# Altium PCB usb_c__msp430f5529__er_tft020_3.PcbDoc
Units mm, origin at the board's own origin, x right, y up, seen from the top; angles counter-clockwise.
Board outline 82 x 52 mm, 2 copper layers (Top, Bottom), stack 0 mm thick; 32 components, 32 nets, 197 pads, 82 vias.
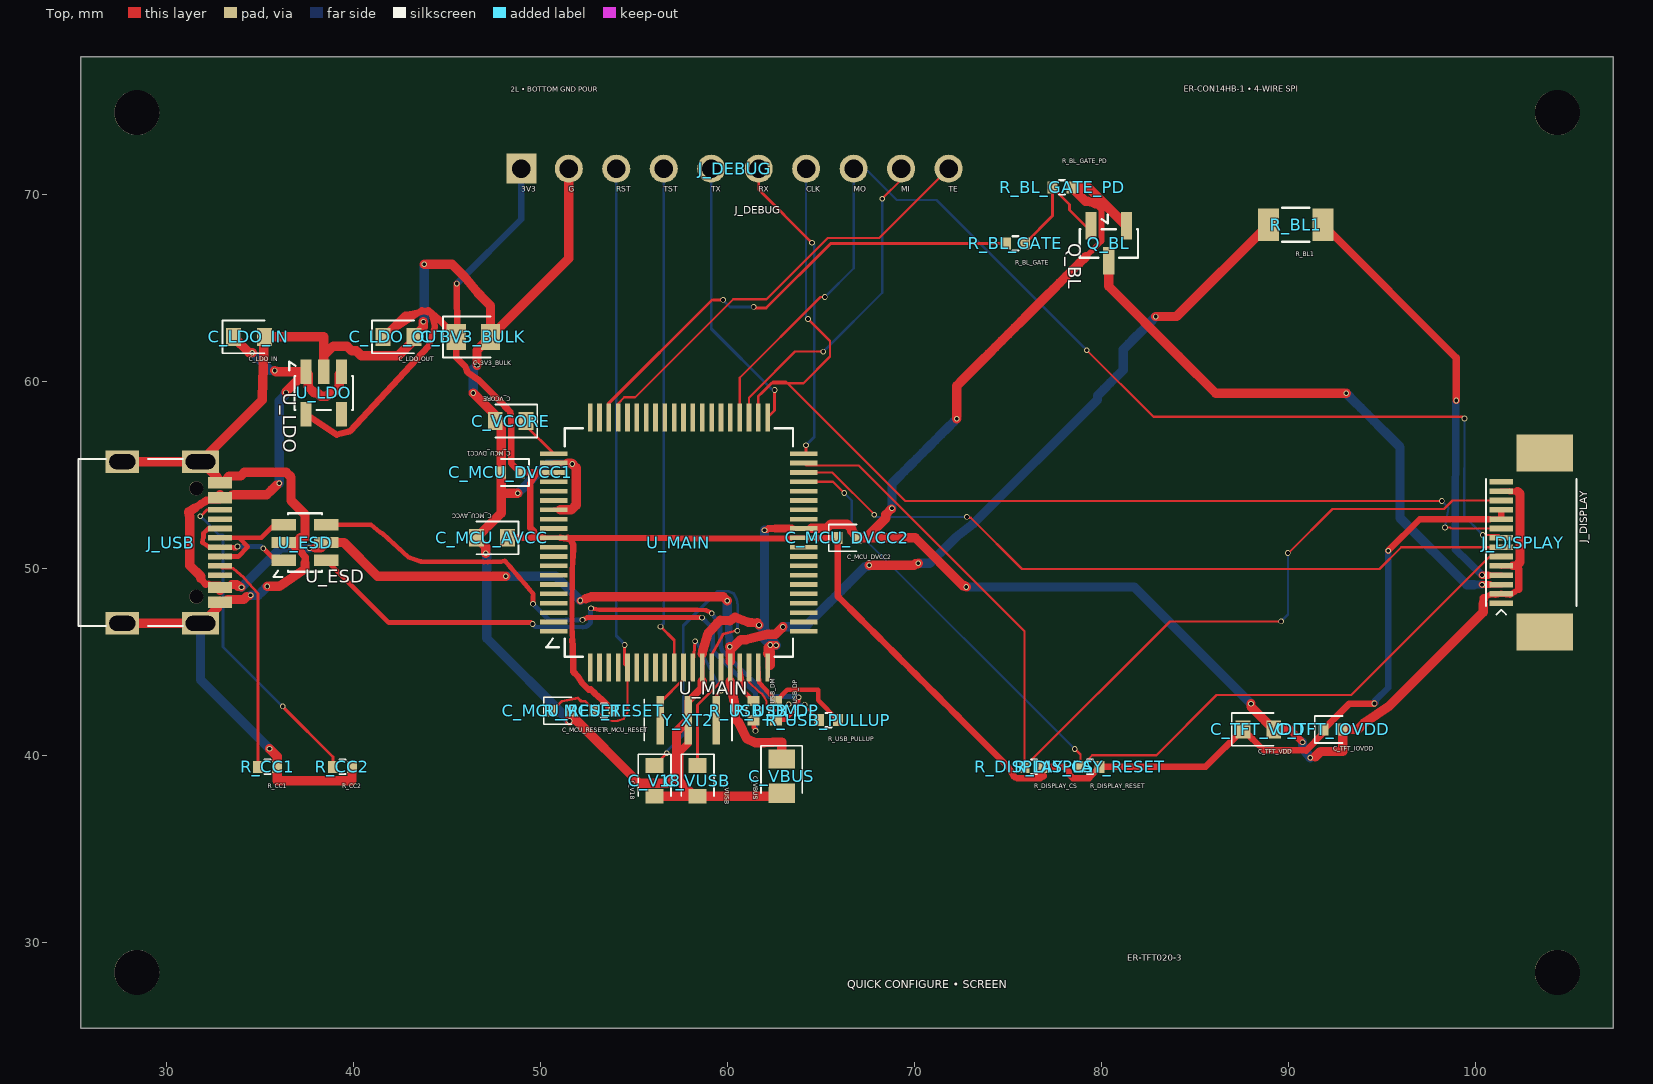
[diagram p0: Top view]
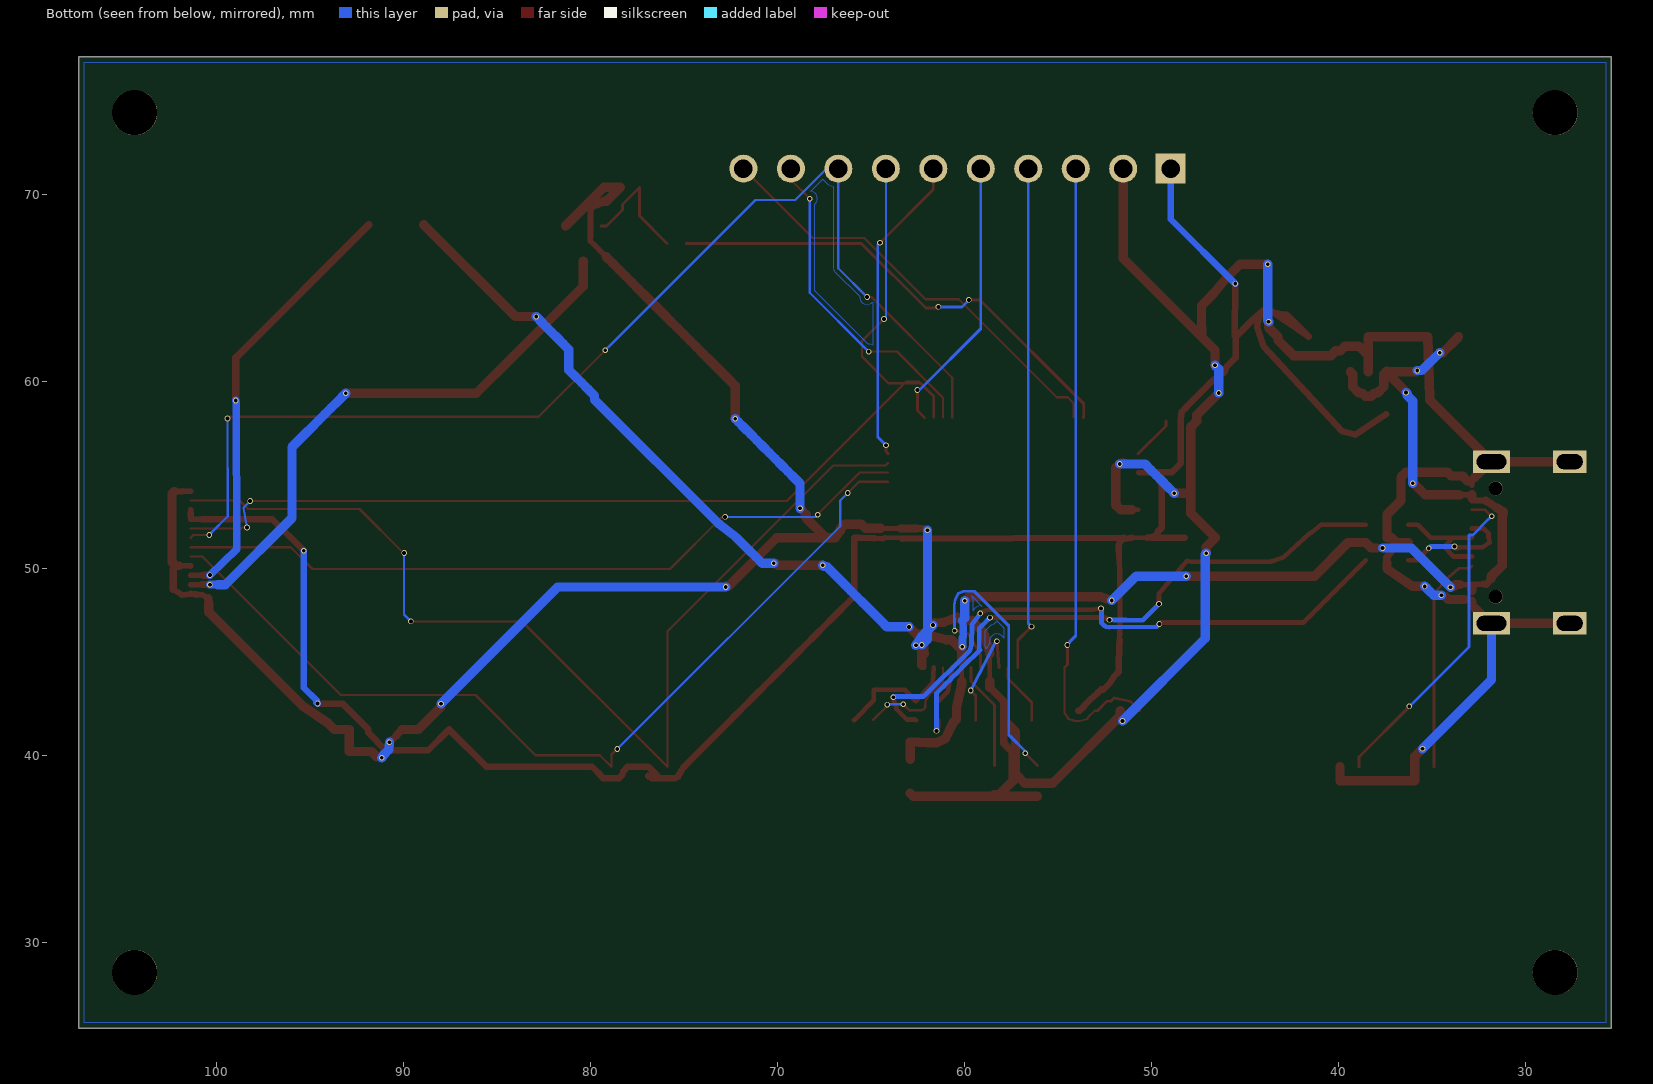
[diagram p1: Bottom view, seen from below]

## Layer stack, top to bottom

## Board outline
25.4,77.4 107.4,77.4 107.4,25.4 25.4,25.4

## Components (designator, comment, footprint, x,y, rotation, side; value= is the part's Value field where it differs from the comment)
C_3V3_BULK "" TSCIRCUIT-2.8500x1.4000mm 46.4,62.4 r0 top
C_LDO_IN "" TSCIRCUIT-2.4500x0.9500mm 34.4,62.4 r0 top
C_LDO_OUT "" TSCIRCUIT-2.4500x0.9500mm 42.4,62.4 r0 top
C_MCU_AVCC "" TSCIRCUIT-2.4500x0.9500mm 47.4,51.65 r180 top
C_MCU_DVCC1 "" TSCIRCUIT-1.5600x0.6400mm 48.4,55.15 r180 top
C_MCU_DVCC2 "" TSCIRCUIT-1.5600x0.6400mm 66.4,51.65 r0 top
C_MCU_RESET "" TSCIRCUIT-1.5600x0.6400mm 51.15,42.4 r0 top
C_TFT_IOVDD "" TSCIRCUIT-1.5600x0.6400mm 92.4,41.4 r0 top
C_TFT_VDD "" TSCIRCUIT-2.4500x0.9500mm 88.4,41.4 r0 top
C_V18 "" TSCIRCUIT-0.9500x2.4500mm 56.1,38.65 r270 top
C_VBUS "" TSCIRCUIT-1.4000x2.8500mm 62.9,38.9 r270 top
C_VCORE "" TSCIRCUIT-2.4500x0.9500mm 48.4,57.9 r180 top
C_VUSB "" TSCIRCUIT-0.9500x2.4500mm 58.4,38.65 r270 top
J_DEBUG "" TSCIRCUIT-24.3600x1.5000mm 60.4,71.4 r0 top
J_DISPLAY "" TSCIRCUIT-4.4500x11.5800mm 103,51.4 r90 top
J_USB "" TSCIRCUIT-6.7732x9.8502mm 30.113,51.4 r90 top
Q_BL "" TSCIRCUIT-2.5000x3.3500mm 80.4,67.4 r270 top
R_BL1 "" TSCIRCUIT-4.0500x1.7500mm 90.4,68.4 r0 top
R_BL_GATE "" TSCIRCUIT-1.5600x0.6400mm 75.4,67.4 r0 top
R_BL_GATE_PD "" TSCIRCUIT-1.5600x0.6400mm 77.9,70.4 r0 top
R_CC1 "" TSCIRCUIT-1.5600x0.6400mm 35.4,39.4 r0 top
R_CC2 "" TSCIRCUIT-1.5600x0.6400mm 39.4,39.4 r0 top
R_DISPLAY_CS "" TSCIRCUIT-1.5600x0.6400mm 76.4,39.4 r0 top
R_DISPLAY_RESET "" TSCIRCUIT-1.5600x0.6400mm 79.4,39.4 r0 top
R_MCU_RESET "" TSCIRCUIT-1.5600x0.6400mm 53.4,42.4 r0 top
R_USB_DM "" TSCIRCUIT-0.6400x1.5600mm 61.4,42.4 r90 top
R_USB_DP "" TSCIRCUIT-0.6400x1.5600mm 62.6,42.4 r90 top
R_USB_PULLUP "" TSCIRCUIT-1.5600x0.6400mm 65.4,41.9 r0 top
U_ESD "" TSCIRCUIT-3.6000x2.5000mm 37.4,51.4 r0 top
U_LDO "" TSCIRCUIT-2.5000x3.6000mm 38.4,59.4 r270 top
U_MAIN "" TSCIRCUIT-14.8500x14.8500mm 57.4,51.4 r0 top
Y_XT2 "" TSCIRCUIT-3.4000x2.6000mm 57.9,41.9 r270 top

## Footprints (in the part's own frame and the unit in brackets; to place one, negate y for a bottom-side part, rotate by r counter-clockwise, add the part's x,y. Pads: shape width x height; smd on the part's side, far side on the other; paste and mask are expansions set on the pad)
TSCIRCUIT-0.6400x1.5600mm [mm]
  rect 0.54x0.64 smd: 1(-0.51,0) 2(0.51,0)
  silkscreen extent -0.15,-0.38 0.15,0.38
TSCIRCUIT-0.9500x2.4500mm [mm]
  rect 0.8x0.95 smd: 1(-0.825,0) 2(0.825,0)
  silkscreen extent -1.43,-0.87 0.82,0.87
TSCIRCUIT-1.4000x2.8500mm [mm]
  rect 1.025x1.4 smd: 1(-0.913,0) 2(0.913,0)
  silkscreen extent -1.62,-1.1 0.91,1.1
TSCIRCUIT-1.5600x0.6400mm [mm]
  rect 0.54x0.64 smd: 1(-0.51,0) 2(0.51,0)
  silkscreen extent -0.98,-0.72 0.51,0.72
TSCIRCUIT-2.4500x0.9500mm [mm]
  rect 0.8x0.95 smd: 1(-0.825,0) 2(0.825,0)
  silkscreen extent -1.43,-0.87 0.82,0.87
TSCIRCUIT-2.5000x3.3500mm [mm]
  rect 1.475x0.6 smd: 1(-0.938,-0.95) 2(-0.938,0.95) 3(0.937,0)
  silkscreen extent -1.54,-1.56 0.76,1.56
TSCIRCUIT-2.5000x3.6000mm [mm]
  rect 1.325x0.6 smd: 1(-1.137,-0.95) 2(-1.137,0) 3(-1.137,0.95) 4(1.138,0.95) 5(1.138,-0.95)
  silkscreen extent -1.69,-1.84 0.91,1.56
TSCIRCUIT-2.8500x1.4000mm [mm]
  rect 1.025x1.4 smd: 1(-0.913,0) 2(0.913,0)
  silkscreen extent -1.63,-1.1 0.91,1.1
TSCIRCUIT-3.4000x2.6000mm [mm]
  rect 2.6x0.4 smd: 1(0,1.5) 2(0,0) 3(0,-1.5)
  silkscreen extent -1.1,-2.35 1.1,2.35
TSCIRCUIT-3.6000x2.5000mm [mm]
  rect 1.325x0.6 smd: 1(-1.137,-0.95) 2(-1.137,0) 3(-1.137,0.95) 4(1.138,0.95) 5(1.138,0) 6(1.138,-0.95)
  silkscreen extent -1.69,-1.84 0.91,1.56
TSCIRCUIT-4.0500x1.7500mm [mm]
  rect 1.125x1.75 smd: 1(-1.462,0) 2(1.463,0)
  silkscreen extent -0.73,-0.91 0.73,0.91
TSCIRCUIT-4.4500x11.5800mm [mm]
  rect 0.3x1.25 smd: 1(-3.25,1.6) 2(-2.75,1.6) 3(-2.25,1.6) 4(-1.75,1.6) 5(-1.25,1.6) 6(-0.75,1.6) 7(-0.25,1.6) 8(0.25,1.6) 9(0.75,1.6) 10(1.25,1.6) 11(1.75,1.6) 12(2.25,1.6) 13(2.75,1.6) 14(3.25,1.6)
  rect 2x3 smd: 15(4.79,-0.725) 16(-4.79,-0.725)
  silkscreen extent -3.85,-2.43 3.4,2.42
TSCIRCUIT-6.7732x9.8502mm [mm]
  rect 0.3x1.3 smd: 1(-3.35,-2.737) 2(-3.05,-2.737) 3(-2.55,-2.737) 4(-2.25,-2.737) 5(-1.75,-2.737) 6(-1.25,-2.737) 7(-0.75,-2.737) 8(-0.25,-2.737) 9(0.25,-2.737) 10(0.75,-2.737) 11(1.25,-2.737) 12(1.75,-2.737) 13(2.55,-2.737) 14(2.25,-2.737) 15(3.35,-2.737) 16(3.05,-2.737)
  rect 1.2x2 hole 0.8 slot 1.6 at 90 deg: 17(-4.325,-1.693) 18(4.325,-1.693)
  rect 1.2x1.8 hole 0.8 slot 1.4 at 90 deg: 19(4.325,2.487) 20(-4.325,2.487)
  round 0.75 hole 0.75 unplated: NPTH-1(-2.9,-1.468) NPTH-2(2.9,-1.468)
  silkscreen extent -4.47,-0.75 4.47,4.83
TSCIRCUIT-14.8500x14.8500mm [mm]
  rect 1.475x0.25 smd: 1(-6.687,-4.75) 2(-6.687,-4.25) 3(-6.687,-3.75) 4(-6.687,-3.25) 5(-6.687,-2.75) 6(-6.687,-2.25) 7(-6.687,-1.75) 8(-6.687,-1.25) 9(-6.687,-0.75) 10(-6.687,-0.25) 11(-6.687,0.25) 12(-6.687,0.75) 13(-6.687,1.25) 14(-6.687,1.75) 15(-6.687,2.25) 16(-6.687,2.75) 17(-6.687,3.25) 18(-6.687,3.75) 19(-6.687,4.25) 20(-6.687,4.75) 41(6.687,4.75) 42(6.687,4.25) 43(6.687,3.75) 44(6.687,3.25) 45(6.687,2.75) 46(6.687,2.25) 47(6.687,1.75) 48(6.687,1.25) 49(6.687,0.75) 50(6.687,0.25) 51(6.687,-0.25) 52(6.687,-0.75) 53(6.687,-1.25) 54(6.687,-1.75) 55(6.687,-2.25) 56(6.687,-2.75) 57(6.687,-3.25) 58(6.687,-3.75) 59(6.687,-4.25) 60(6.687,-4.75)
  rect 0.25x1.475 smd: 21(-4.75,6.687) 22(-4.25,6.687) 23(-3.75,6.687) 24(-3.25,6.687) 25(-2.75,6.687) 26(-2.25,6.687) 27(-1.75,6.687) 28(-1.25,6.687) 29(-0.75,6.687) 30(-0.25,6.687) 31(0.25,6.687) 32(0.75,6.687) 33(1.25,6.687) 34(1.75,6.687) 35(2.25,6.687) 36(2.75,6.687) 37(3.25,6.687) 38(3.75,6.687) 39(4.25,6.687) 40(4.75,6.687) 61(4.75,-6.687) 62(4.25,-6.687) 63(3.75,-6.687) 64(3.25,-6.687) 65(2.75,-6.687) 66(2.25,-6.687) 67(1.75,-6.687) 68(1.25,-6.687) 69(0.75,-6.687) 70(0.25,-6.687) 71(-0.25,-6.687) 72(-0.75,-6.687) 73(-1.25,-6.687) 74(-1.75,-6.687) 75(-2.25,-6.687) 76(-2.75,-6.687) 77(-3.25,-6.687) 78(-3.75,-6.687) 79(-4.25,-6.687) 80(-4.75,-6.687)
  silkscreen extent -7.09,-6.11 6.11,6.11
TSCIRCUIT-24.3600x1.5000mm [mm]
  rect 1.6x1.6 hole 1: 1(-11.43,0)
  round 1.5 hole 1: 2(-8.89,0) 3(-6.35,0) 4(-3.81,0) 5(-1.27,0) 6(1.27,0) 7(3.81,0) 8(6.35,0) 9(8.89,0) 10(11.43,0)

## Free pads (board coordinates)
  round 2.4 hole 2.4 unplated: NPTH-3(28.4,28.4) NPTH-4(104.4,28.4) NPTH-5(28.4,74.4) NPTH-6(104.4,74.4)

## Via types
v1: diameter 0.3, hole 0.2, Top to Bottom, 82 vias

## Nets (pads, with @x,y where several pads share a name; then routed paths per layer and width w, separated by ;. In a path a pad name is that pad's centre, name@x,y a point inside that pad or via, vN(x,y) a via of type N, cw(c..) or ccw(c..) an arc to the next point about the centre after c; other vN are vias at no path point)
".J_DEBUG > .pin4 to .U_MAIN > .pin71": J_DEBUG.4 U_MAIN.71 | length 27.1
  Top w0.15: v1(56.417,46.902) 57.15,46.169 U_MAIN.71
  Bottom w0.15: v1@56.416,46.903 56.416,46.906 56.59,47.08 J_DEBUG.4
".J_DEBUG > .pin5 to .U_MAIN > .pin40": J_DEBUG.5 U_MAIN.40 | length 15
  Top w0.15: U_MAIN.40 62.521,58.458 v1(62.521,59.561)
  Bottom w0.15: J_DEBUG.5 59.13,62.834 62.427,59.537 62.497,59.537 v1(62.521,59.561)
".J_DEBUG > .pin6 to .U_MAIN > .pin41": J_DEBUG.6 U_MAIN.41 | length 16.7
  Top w0.15: J_DEBUG.6 61.67,70.293 64.423,67.54 64.423,67.535 v1(64.524,67.434) ; U_MAIN.41 64.2,56.262 v1(64.2,56.6)
  Bottom w0.15: v1(64.2,56.6) 64.645,57.045 64.646,57.163 64.646,67.313 v1(64.524,67.434)
BACKLIGHT_ANODE_1: J_DISPLAY.4 R_BL1.2 | length 23.3
  Top w0.3: 100.775,49.65 100.8,49.65 100.9,49.65 101,49.65 101.1,49.65 101.2,49.65 101.3,49.65 J_DISPLAY.4
  Top w0.343: 100.7,49.65 100.775,49.65
  Top w0.4: R_BL1.2 98.991,61.272 v1(98.991,59) ; v1(100.372,49.658) 100.4,49.65 100.6,49.65 100.7,49.65
  Bottom w0.4: v1(98.991,59) 98.993,58.998 98.97,58.914 98.934,51.028 v1(100.372,49.658)
BACKLIGHT_CATHODE: J_DISPLAY.3 Q_BL.3 | length 31.2
  Top w0.3: 100.775,49.15 100.837,49.15 101.119,49.15 J_DISPLAY.3
  Top w0.375: v1(100.372,49.143) 100.4,49.15 100.65,49.15 100.744,49.15
  Top w0.387: 100.744,49.15 100.775,49.15
  Top w0.5: Q_BL.3 80.4,65.105 84.147,61.358 86.122,59.383 v1(93.101,59.383)
  Bottom w0.425: 99.96,49.144 v1(100.372,49.143)
  Bottom w0.5: v1(93.101,59.383) 93.17,59.314 93.522,58.962 93.873,58.611 94.224,58.26 94.576,57.908 94.927,57.557 95.278,57.206 95.63,56.854 95.981,56.503 95.981,52.712 99.547,49.145 99.96,49.144
BACKLIGHT_GATE: Q_BL.1 R_BL_GATE.2 R_BL_GATE_PD.1 | length 6.7
  Top w0.15: R_BL_GATE.2 77.39,68.88 R_BL_GATE_PD.1 78.301,69.489 78.301,69.184 79.147,68.338 Q_BL.1
BACKLIGHT_PWM: R_BL_GATE.1 U_MAIN.23 | length 25.9
  Top w0.15: U_MAIN.23 53.619,58.118 53.619,58.822 59.177,64.38 v1(59.764,64.38) ; v1(61.395,64.004) 61.452,63.947 62.07,63.947 65.523,67.4 R_BL_GATE.1
  Bottom w0.15: v1(59.764,64.38) 59.792,64.352 60.14,64.004 v1(61.395,64.004)
DISPLAY_CS_N: J_DISPLAY.12 R_DISPLAY_CS.1 U_MAIN.42 | length 56.1
  Top w0.12: U_MAIN.42 64.225,55.513 67.031,55.513 75.89,46.654 R_DISPLAY_CS.1 83.668,47.178 v1(89.617,47.178) ; v1(89.984,50.836) 90.024,50.876 90.049,50.876 92.369,53.196 98.338,53.196 98.792,53.65 J_DISPLAY.12
  Bottom w0.12: v1(89.617,47.178) 89.661,47.222 89.984,47.545 v1(89.984,50.836)
DISPLAY_DC: J_DISPLAY.7 U_MAIN.43 | length 39.9
  Top w0.12: U_MAIN.43 65.61,55.15 67.854,52.906 v1(67.854,52.884) ; v1(72.808,52.769) 72.859,52.718 73.016,52.718 75.75,49.984 94.883,49.984 96.049,51.15 J_DISPLAY.7
  Bottom w0.12: v1(67.854,52.884) 67.858,52.88 67.969,52.769 v1(72.808,52.769)
DISPLAY_MISO: J_DEBUG.9 U_MAIN.38 | length 17.6
  Top w0.12: U_MAIN.38 61.15,59.147 61.458,59.455 63.617,61.614 v1(65.122,61.614) ; v1(68.278,69.797) 68.294,69.813 69.29,70.809 J_DEBUG.9
  Bottom w0.12: v1(65.122,61.614) 65.291,61.783 65.297,61.783 68.278,64.764 v1(68.278,69.797)
DISPLAY_MOSI: J_DEBUG.8 J_DISPLAY.8 U_MAIN.37 | length 61.9
  Top w0.12: U_MAIN.37 60.65,60.213 64.97,64.533 v1(65.212,64.533) ; v1(79.225,61.691) 82.789,58.127 99.247,58.127 99.322,58.127 v1(99.431,58.035) ; v1(100.4,51.8) 101.25,51.8 J_DISPLAY.8
  Bottom w0.12: v1(65.212,64.533) 65.215,64.536 66.75,66.071 J_DEBUG.8 67.379,71.4 69.055,69.724 71.176,69.724 79.045,61.854 79.062,61.854 v1(79.225,61.691) ; v1(99.431,58.035) 99.414,52.808 100.288,51.934 100.288,51.912 v1(100.4,51.8)
DISPLAY_RESET_N: J_DISPLAY.6 R_DISPLAY_RESET.1 U_MAIN.44 | length 49.5
  Top w0.12: U_MAIN.44 65.648,54.65 v1(66.248,54.05) ; v1(78.572,40.353) 78.625,40.3 78.648,40.3 78.89,40.058 R_DISPLAY_RESET.1 79.513,40.023 82.951,40.023 86.167,43.238 93.369,43.238 100.062,49.932 100.78,50.65 J_DISPLAY.6
  Bottom w0.12: v1(66.248,54.05) 66.287,54.011 66.65,53.648 66.65,53.413 66.65,52.275 v1(78.572,40.353)
DISPLAY_SCLK: J_DEBUG.7 J_DISPLAY.9 U_MAIN.39 | length 61.7
  Top w0.12: v1(64.306,63.357) 65.484,62.182 65.484,61.345 64.064,59.925 62.331,59.925 61.65,59.244 U_MAIN.39 61.65,59.2 61.87,59.419 62.462,60.011 63.122,60.011 69.515,53.618 v1(98.22,53.618) ; v1(98.388,52.203) 98.592,52.197 98.669,52.197 98.716,52.15 J_DISPLAY.9
  Bottom w0.12: J_DEBUG.7 64.197,71.387 64.197,63.656 64.197,63.469 v1(64.306,63.357) ; v1(98.22,53.618) 98.269,53.569 98.569,53.252 v1(98.388,52.203)
DISPLAY_TE: J_DEBUG.10 U_MAIN.24 | length 23.6
  Top w0.12: U_MAIN.24 54.15,58.836 54.482,59.169 55.059,59.169 60.307,64.417 62.089,64.417 65.365,67.694 68.124,67.694 J_DEBUG.10
GND: C_3V3_BULK.2 C_LDO_IN.2 C_LDO_OUT.2 C_MCU_AVCC.2 C_MCU_DVCC1.2 C_MCU_DVCC2.2 C_MCU_RESET.2 C_TFT_IOVDD.2 C_TFT_VDD.2 C_V18.2 C_VBUS.2 C_VCORE.2 C_VUSB.2 J_DEBUG.2 J_DISPLAY.2 J_DISPLAY.5 J_DISPLAY.13 J_USB.1 J_USB.2 J_USB.15 J_USB.16 J_USB.17 J_USB.18 J_USB.19 J_USB.20 Q_BL.2 R_BL_GATE_PD.2 R_CC1.2 R_CC2.2 U_ESD.2 U_LDO.2 U_MAIN.14 U_MAIN.19 U_MAIN.49 U_MAIN.61 U_MAIN.68 Y_XT2.2 | length 248.6
  Top w0.25: U_MAIN.14 U_MAIN.14@51.044,53.15 ; U_MAIN.68@58.65,43.975 U_MAIN.68 U_MAIN.68@58.65,44.806 ; 62.15,45.45 62.15,45.369 62.15,45.275 62.15,45.181 62.15,45.087 62.15,44.994 62.15,44.9 62.15,44.806 U_MAIN.61 U_MAIN.61@62.275,44.837 ; U_MAIN.49@63.431,52.15 63.525,52.15 63.619,52.15 63.712,52.15 63.806,52.15 63.9,52.15 63.994,52.15 U_MAIN.49 ; U_MAIN.19 51.45,55.65 51.369,55.65 51.275,55.65 51.181,55.65 51.088,55.65 50.994,55.65 50.9,55.65 50.806,55.65 U_MAIN.19
  Top w0.255: U_MAIN.68@58.65,44.806 U_MAIN.68@58.654,44.9
  Top w0.263: U_MAIN.68@58.651,45.181 58.652,45.087 U_MAIN.68@58.653,44.993
  Top w0.264: U_MAIN.68@58.651,45.181 58.65,45.274 U_MAIN.68@58.657,45.45 ; U_MAIN.68@58.654,44.9 U_MAIN.68@58.653,44.993
  Top w0.269: U_MAIN.49 U_MAIN.49@64.494,52.155
  Top w0.275: J_USB.1@32.849,48.2 J_USB.2 J_USB.2@33.273,48.35 ; J_USB.16 J_USB.15@33.101,54.702 ; 79.507,67.025 79.852,67.37 80.025,67.525
  Top w0.288: J_USB.16 J_USB.15@32.849,54.6
  Top w0.3: J_USB.1@32.699,47.9 J_USB.1 J_USB.2@32.849,48.2 ; 32.699,54.9 J_USB.15 J_USB.16@32.849,54.6 ; 79.162,66.68 79.507,67.025 ; J_DISPLAY.5 101.791,50.15 102.15,50.15 ; J_DISPLAY.13 J_DISPLAY.13@101.838,54.142
  Top w0.312: 79.681,69.525 80.012,69.194 80.012,67.863 80.025,67.525 ; 100.462,48.431 100.775,48.587 J_DISPLAY.2@101.087,48.619 ; J_DISPLAY.2@101.869,48.587 102.103,48.744 102.337,48.9
  Top w0.316: J_DISPLAY.5 101.801,50.155 J_DISPLAY.5@102.025,50.158
  Top w0.322: J_DISPLAY.13@101.838,54.142 102.275,54.134
  Top w0.325: v1(61.983,52.06) 62.043,52.077 v1@62.118,52.077 ; v1@90.712,40.766 90.712,40.743 v1(90.767,40.718) ; v1(91.182,39.886) 91.436,39.926 ; J_DISPLAY.2 J_DISPLAY.2@101.869,48.587
  Top w0.35: v1@62.118,52.077 62.19,52.15 62.573,52.15 ; J_DISPLAY.2@101.087,48.619 J_DISPLAY.2
  Top w0.375: 34.282,48.512 34.426,48.512 v1(34.488,48.574) ; 90.395,41.083 v1@90.712,40.766 ; 102.15,50.15 102.337,49.963
  Top w0.4: 37,51.2 37.2,50.9 37.4,50.6 37.4,50.3 ; 57.4,40.15 57.9,40.65 Y_XT2.2 ; Y_XT2.2@57.7,41.7 Y_XT2.2 ; 58.65,43.65 57.9,42.9 Y_XT2.2 ; v1@68.769,53.201 v1(68.798,53.23) ; 102.337,48.9 102.337,49.291 102.337,49.963
  Top w0.425: 90.079,41.4 90.395,41.083
  Top w0.437: 62.15,45.78 62.278,45.909 v1(62.6,45.9) ; 62.288,45.562 v1(62.288,45.918) ; 62.573,52.15 63.002,52.15 U_MAIN.49@63.431,52.15
  Top w0.45: 62.15,45.462 62.15,45.78 ; 100.425,48.115 100.462,48.431
  Top w0.475: v1@61.597,47.098 v1(61.688,46.983) ; 68.478,52.87 68.457,52.891 v1@68.768,53.201 ; 102.025,50.158 102.202,50.16 ; 102.275,54.134 102.4,54.009
  Top w0.5: J_USB.20 J_USB.17 31.874,47.075 32.474,47.675 J_USB.1@32.699,47.9 ; J_USB.19 J_USB.18 ; 32.699,54.9 32.474,55.125 31.874,55.725 J_USB.18 ; J_USB.15@33.101,54.702 33.353,54.954 33.827,54.954 33.954,54.954 34.15,55.15 36.4,55.15 36.65,54.9 36.65,53.65 37.4,52.9 37.4,51.65 37.15,51.65 36.9,51.4 U_ESD.2 ; J_USB.2@33.273,48.35 33.696,48.35 34.12,48.35 34.282,48.512 ; v1(35.379,49.052) 35.703,49.052 36.028,49.052 37.4,50 37.4,50.3 ; v1(35.498,40.362) 35.91,39.95 R_CC1.2 35.91,38.65 39.91,38.65 R_CC2.2 ; U_ESD.2 36.649,51.4 36.901,51.149 37,51.2 ; v1(43.732,63.208) 43.732,62.907 C_LDO_OUT.2 43.225,62.225 42.4,61.4 40.4,61.4 40.15,61.65 39.9,61.65 39.65,61.9 38.9,61.9 38.4,61.4 U_LDO.2 38.4,62.4 C_LDO_IN.2 35.106,59.146 35.106,59.025 J_USB.18 ; v1(43.783,66.292) 45.258,66.292 45.9,65.65 46.651,64.744 46.988,64.405 47.324,64.065 47.321,63.649 47.318,63.233 47.315,62.816 C_3V3_BULK.2 ; v1(46.4,59.4) 47.575,58.225 C_VCORE.2 47.89,57.585 47.89,57.098 47.89,56.611 47.89,56.124 47.89,55.637 C_MCU_DVCC1.2 ; v1(46.602,60.884) 46.602,61.69 C_3V3_BULK.2 ; v1(47.068,50.824) 47.068,51.157 C_MCU_AVCC.2 47.89,52.965 C_MCU_DVCC1.2 ; v1(48.778,54.03) 47.89,54.03 C_MCU_DVCC1.2 ; U_MAIN.14@51.044,53.15 51.65,53.15 51.9,53.4 51.9,55.4 51.65,55.65 51.45,55.65 51.463,55.65 51.642,55.65 51.692,55.6 v1(51.7,55.6) ; J_DEBUG.2 51.51,66.597 C_3V3_BULK.2 ; v1(51.55,41.85) 51.55,41.946 51.66,42.056 C_MCU_RESET.2 51.66,42.14 55.275,38.525 56.775,38.525 57.275,39.025 57.275,41.275 57.7,41.7 ; C_V18.2 C_VUSB.2 ; 57.4,40.15 57.4,38.65 58.15,37.9 58.4,37.9 C_VUSB.2 ; 58.65,43.65 U_MAIN.68@58.65,43.975 ; 58.657,45.45 58.662,45.567 58.956,46.538 59.217,46.819 59.478,47.1 59.619,47.244 60.113,47.207 60.4,47.4 61.102,47.134 v1@61.597,47.098 ; 62.15,45.45 62.15,45.462 ; 62.275,44.837 62.288,44.85 62.288,45.206 62.288,45.562 ; C_VBUS.2 62.737,37.825 C_VUSB.2 ; U_MAIN.49@64.494,52.155 64.9,52.16 65.301,52.16 65.525,52.384 65.962,52.384 66.4,52.384 66.655,52.129 66.655,52.017 C_MCU_DVCC2.2 ; 68.478,52.87 68.478,52.713 67.416,51.65 C_MCU_DVCC2.2 ; v1(72.261,58.017) 72.261,58.458 72.261,58.898 72.261,59.339 72.261,59.779 72.606,60.124 72.951,60.469 73.296,60.814 73.641,61.159 73.986,61.504 74.331,61.849 74.676,62.194 75.021,62.54 75.366,62.885 75.711,63.23 76.056,63.575 76.401,63.92 76.746,64.265 77.091,64.61 77.436,64.955 77.781,65.3 78.127,65.645 78.472,65.99 78.817,66.335 79.162,66.68 ; v1(72.768,49.018) 72.694,49.092 72.6,49.092 70.042,51.65 C_MCU_DVCC2.2 ; 79.681,69.525 79.275,69.657 79.153,69.657 R_BL_GATE_PD.2 79.287,70.4 Q_BL.2 ; v1(88.008,42.775) 88.008,42.617 C_TFT_VDD.2 89.652,41.4 90.079,41.4 ; 91.436,39.926 91.731,40.221 92.91,40.221 C_TFT_IOVDD.2 93.312,41.397 93.713,41.395 94.066,41.748 95.4,42.65 100.425,47.675 100.425,48.115 ; 102.202,50.16 102.4,50.358 102.4,50.4 102.4,54.009
  Bottom w0.5: J_USB.17 31.806,44.054 v1(35.498,40.362) ; v1(34.488,48.574) 34.894,48.574 35.104,48.783 35.313,48.993 35.32,48.993 v1(35.379,49.052) ; v1(43.732,63.208) 43.783,63.259 v1(43.783,66.292) ; v1(46.4,59.4) 46.4,60.68 46.555,60.835 46.555,60.837 v1(46.602,60.884) ; v1(47.068,50.824) 47.121,50.77 47.121,46.279 v1(51.55,41.85) ; v1(48.778,54.03) 48.831,54.083 49.134,54.386 49.438,54.69 49.741,54.993 50.045,55.297 50.348,55.6 50.799,55.6 51.249,55.6 v1(51.7,55.6) ; v1(61.688,46.983) 61.734,46.937 62.011,46.66 62.288,46.383 v1(62.6,45.9) ; v1(61.983,52.06) 61.983,46.223 v1(62.288,45.918) ; v1(68.798,53.23) 68.798,53.671 68.798,54.113 68.798,54.554 69.129,54.884 69.459,55.215 69.79,55.546 70.12,55.876 70.451,56.207 70.781,56.537 71.112,56.868 71.443,57.198 71.773,57.529 72.104,57.86 v1(72.261,58.017) ; v1(72.768,49.018) 81.765,49.018 v1@87.93,42.853 ; v1@87.93,42.853 v1(88.008,42.775) ; v1(90.767,40.718) 90.8,40.313 91.088,40.025 91.088,39.998 v1(91.182,39.886)
MAIN_RESET: C_MCU_RESET.1 J_DEBUG.3 R_MCU_RESET.1 U_MAIN.76 | length 34.3
  Top w0.12: R_MCU_RESET.1 53.032,42.4 53.4,42.032 53.422,41.957 53.824,41.85 54.129,41.867 54.447,41.961 54.65,42.291 U_MAIN.76
  Top w0.15: C_MCU_RESET.1 51.152,42.912 52,43.075 52.177,42.912 52.378,42.912 R_MCU_RESET.1 ; v1(54.495,45.914) 54.495,44.867 U_MAIN.76
  Bottom w0.15: J_DEBUG.3 54.05,46.411 54.368,46.093 54.368,46.041 v1(54.495,45.914)
MSP_USB_PUR: R_USB_PULLUP.1 U_MAIN.63 | length 5.9
  Top w0.12: U_MAIN.63 61.15,43.919 61.664,43.437 61.848,43.302 62.013,43.076 62.09,42.895 62.107,42.572 62.184,42.485 62.28,42.43 62.92,42.43 62.921,42.399 63.109,42.578 v1(63.28,42.745) ; v1(64.139,42.73) 64.119,42.671 R_USB_PULLUP.1
  Bottom w0.12: v1(63.28,42.745) 64.053,42.743 64.056,42.74 64.118,42.74 v1(64.139,42.73)
MSP_V18: C_V18.1 U_MAIN.67 | length 16.4
  Top w0.15: C_V18.1 56.728,40.103 v1(56.746,40.12) ; U_MAIN.67 59.15,45.393 59.783,46.505 60.437,46.679 60.446,46.679 v1(60.53,46.679)
  Bottom w0.15: v1(56.746,40.12) 56.717,40.173 56.686,40.173 57.631,41.117 57.631,46.945 59.478,48.792 60.049,48.792 60.334,48.672 60.495,48.346 60.549,48.068 v1(60.53,46.679)
MSP_VCORE: C_VCORE.1 U_MAIN.20 | length 2.4
  Top w0.15: C_VCORE.1 49.225,57.638 U_MAIN.20
MSP_VUSB: C_VUSB.1 U_MAIN.66 | length 5.8
  Top w0.15: C_VUSB.1 58.4,42.713 59.657,43.97 59.657,44.705 U_MAIN.66
usb-dm-mcu: R_USB_DM.2 U_MAIN.64 | length 2
  Top w0.25: U_MAIN.64 60.9,43.41 R_USB_DM.2
usb-dm-phy: R_USB_DM.1 U_ESD.4 | length 30.6
  Top w0.238: 46.934,50.367 46.95,50.35 47.18,50.357
  Top w0.25: U_ESD.4 38.546,52.342 38.784,52.342 39.023,52.343 39.261,52.343 39.5,52.343 39.738,52.343 39.977,52.343 40.215,52.344 40.454,52.344 40.692,52.344 40.931,52.344 41.091,52.211 41.252,52.078 41.412,51.944 41.525,51.9 42.937,50.616 43.16,50.537 43.383,50.459 43.606,50.38 43.844,50.379 44.081,50.378 44.319,50.377 44.557,50.376 44.795,50.375 45.032,50.374 45.27,50.373 45.508,50.372 45.745,50.371 45.983,50.37 46.221,50.369 46.459,50.368 46.696,50.368 46.934,50.367 ; 47.18,50.357 47.409,50.365 47.647,50.364 47.885,50.363 48.085,50.429 48.237,50.252 48.388,50.075 48.54,49.898 48.692,49.722 48.844,49.545 48.995,49.368 49.147,49.191 49.299,49.015 49.45,48.838 49.602,48.661 49.599,48.479 49.597,48.297 v1(49.594,48.115) ; v1(52.244,47.259) 52.318,47.314 52.415,47.314 52.485,47.384 52.731,47.384 52.977,47.384 53.223,47.384 53.469,47.384 53.715,47.384 53.961,47.384 54.207,47.384 54.453,47.384 54.699,47.384 54.945,47.384 55.19,47.384 55.436,47.384 55.682,47.384 55.928,47.384 56.174,47.384 56.42,47.384 56.666,47.384 56.912,47.384 57.158,47.384 57.404,47.384 57.65,47.384 57.896,47.384 58.142,47.384 58.388,47.384 v1(58.634,47.384) ; R_USB_DM.1 61.4,41.698 61.4,41.506 61.482,41.424 61.482,41.339 v1(61.5,41.321)
  Bottom w0.25: v1(49.594,48.115) 49.608,48.101 49.78,47.929 49.952,47.757 50.125,47.584 50.297,47.412 50.469,47.24 50.691,47.242 50.913,47.245 51.135,47.247 51.356,47.25 51.578,47.252 51.8,47.255 52.022,47.257 v1(52.244,47.259) ; v1(58.634,47.384) 58.637,47.381 58.781,47.237 58.924,47.094 59.068,46.95 59.211,46.807 59.211,46.57 59.211,46.333 59.211,46.096 59.211,45.859 59.211,45.622 59.15,45.65 60.092,44.742 60.268,44.566 60.444,44.39 60.62,44.214 60.796,44.037 60.972,43.861 61.148,43.685 61.324,43.509 61.5,43.333 61.5,43.11 61.5,42.886 61.5,42.663 61.5,42.439 61.5,42.215 61.5,41.992 61.5,41.768 61.5,41.545 v1(61.5,41.321)
usb-dm-port: J_USB.7 J_USB.9 U_ESD.3 | length 7.1
  Top w0.25: J_USB.7 33.815,50.65 34.342,51.176 33.867,51.654 J_USB.9 35.066,51.65 35.764,52.348 36.261,52.348 U_ESD.3
usb-dp-mcu: R_USB_DP.2 R_USB_PULLUP.2 U_MAIN.62 | length 6.7
  Top w0.25: U_MAIN.62 61.702,43.909 R_USB_DP.2 63.196,43.518 64.853,43.513 64.853,42.957 R_USB_PULLUP.2
usb-dp-phy: R_USB_DP.1 U_ESD.6 | length 32.2
  Top w0.25: U_ESD.6 41.869,47.118 49.407,47.118 49.497,47.118 v1(49.572,47.043) ; v1(52.7,47.874) 53.14,47.801 54.899,47.8 57.098,47.794 58.417,47.795 58.829,47.779 59.097,47.65 59.115,47.65 v1(59.16,47.605) ; R_USB_DP.1 62.64,41.93 63.08,41.93 63.639,42.489 63.669,42.715 63.784,42.891 v1(63.804,43.126)
  Bottom w0.25: v1(49.572,47.043) 49.727,46.888 52.256,46.869 52.447,46.888 52.489,46.93 52.676,47.117 52.676,47.85 52.676,47.866 v1(52.7,47.874) ; v1(59.16,47.605) 59.601,47.005 59.623,45.956 59.719,45.604 62.199,43.157 63.797,43.157 63.797,43.152 v1(63.804,43.126)
usb-dp-port: J_USB.8 J_USB.10 U_ESD.1 | length 6.3
  Top w0.25: J_USB.10 32.645,52.15 32.442,52.15 32.238,52.15 31.962,51.9 31.963,51.875 31.963,51.669 31.9,51.4 32.275,51.15 J_USB.8 33.543,51.15 33.582,51.11 33.711,51.11 v1(33.785,51.184) ; v1(35.162,51.084) 35.797,50.45 U_ESD.1
  Bottom w0.25: v1(33.785,51.184) 35.039,51.191 35.041,51.189 35.058,51.189 v1(35.162,51.084)
USB_CC1: J_USB.6 R_CC1.1 | length 11.9
  Top w0.15: J_USB.6 32.976,50.023 33.546,50.023 34.132,49.508 34.89,48.678 R_CC1.1
USB_CC2: J_USB.12 R_CC2.1 | length 17.7
  Top w0.15: v1(31.799,52.8) 32.149,53.15 J_USB.12 ; v1(36.203,42.631) 36.263,42.571 36.263,42.562 38.89,39.934 R_CC2.1
  Bottom w0.15: v1(31.799,52.8) 31.948,52.651 31.963,52.651 32.804,51.809 33.015,51.809 33.015,45.819 v1(36.203,42.631)
VBUS5: C_LDO_IN.1 C_VBUS.1 J_USB.3 J_USB.4 J_USB.13 J_USB.14 R_BL1.1 U_ESD.5 U_LDO.1 U_LDO.3 U_MAIN.65 | length 105.9
  Top w0.25: U_MAIN.65@60.15,43.975 U_MAIN.65 ; U_MAIN.65@60.15,45.033 U_MAIN.65 ; U_MAIN.65@60.15,45.45 U_MAIN.65
  Top w0.3: 32.129,53.65 32.489,53.65 J_USB.14 32.849,53.8 ; J_USB.4@32.235,49.171 32.532,49.171 32.828,49.171 J_USB.4 ; J_USB.3@32.849,49 J_USB.4 ; J_USB.13 32.943,53.95 33.037,53.95 33.13,53.95 33.224,53.95 33.318,53.95 33.412,53.95 33.499,53.95 ; 33.499,49.15 33.412,49.15 33.318,49.15 33.224,49.15 33.13,49.15 33.037,49.15 32.943,49.15 J_USB.4
  Top w0.325: v1(37.632,51.105) U_ESD.5@37.937,51.105
  Top w0.35: 35.881,54.477 35.918,54.477 v1(36.015,54.574)
  Top w0.375: 31.828,49.494 32.087,49.15 J_USB.4@32.235,49.171
  Top w0.4: v1(52.124,48.295) 52.418,48.394
  Top w0.425: 33.815,49.069 33.931,49.069 v1(34,49)
  Top w0.437: 31.497,53.244 31.813,53.447 32.129,53.65
  Top w0.475: 33.499,49.15 33.505,49.15 33.599,49.15 ; 33.499,53.95 33.505,53.95 33.599,53.95
  Top w0.5: 31.497,53.244 31.181,53.041 31.234,52.755 31.234,52.325 31.234,51.894 31.234,51.464 31.234,51.033 31.234,50.603 31.234,50.172 31.828,49.578 31.828,49.494 ; J_USB.3 J_USB.4@32.849,49 ; J_USB.13@32.849,53.8 J_USB.13 ; C_LDO_IN.1 34.419,61.556 v1(34.579,61.556) ; 33.599,49.15 33.734,49.15 33.815,49.069 ; 33.599,53.95 34.038,53.95 34.476,53.95 34.915,53.95 35.354,53.95 35.617,54.214 35.881,54.477 ; v1(35.774,60.599) 35.836,60.537 U_LDO.1 ; v1(36.383,59.422) 36.383,59.471 U_LDO.1 ; U_ESD.5@37.937,51.105 38.242,51.105 U_ESD.5 39.009,51.399 39.481,51.398 41.28,49.599 v1(48.14,49.599) ; U_LDO.3 39.35,60.517 39.233,60.4 39.233,59.733 38.9,59.4 38.733,59.4 38.567,59.233 38.233,59.233 38.067,59.4 37.9,59.4 37.567,59.733 37.567,60.4 37.4,60.567 37.421,60.567 U_LDO.1 ; 52.418,48.394 52.713,48.494 59.775,48.494 v1(59.984,48.285) ; v1(60.122,45.822) 60.15,45.794 60.15,45.45 ; U_MAIN.65@60.15,43.975 60.15,43.759 60.166,43.744 60.253,43.35 60.341,42.956 60.428,42.563 60.428,41.95 60.603,41.775 60.822,41.337 61.041,40.9 61.478,40.681 61.952,40.696 62.426,40.711 62.9,40.726 62.9,40.269 C_VBUS.1 ; U_MAIN.65@60.15,45.033 60.15,45.65 60.707,46.207 61.003,46.207 62.144,46.491 62.572,46.491 62.9,46.819 v1(62.967,46.886) ; v1(67.591,50.189) 68.069,50.189 68.547,50.189 69.025,50.189 69.503,50.189 69.981,50.189 70.057,50.265 70.184,50.265 v1(70.208,50.289) ; v1(82.912,63.488) 84.026,63.488 R_BL1.1
  Bottom w0.375: 60.066,46.349 60.111,46.304 ; 60.066,46.881 60.108,47.236
  Bottom w0.4: 60.066,46.349 60.066,46.881
  Bottom w0.425: 60.111,46.304 60.113,45.838 v1(60.122,45.822)
  Bottom w0.475: 59.984,47.36 60.108,47.236
  Bottom w0.5: v1(34,49) 36.105,51.105 v1(37.632,51.105) ; v1(34.579,61.556) 35.537,60.599 v1(35.774,60.599) ; v1(36.015,54.574) 36.015,55.062 36.015,55.55 36.015,56.038 36.015,56.526 36.015,57.015 36.015,57.503 36.015,57.991 36.015,58.479 36.015,58.967 36.311,59.263 36.311,59.35 v1(36.383,59.422) ; v1(48.14,49.599) 50.82,49.599 v1(52.124,48.295) ; 59.984,47.36 v1(59.984,48.285) ; v1(62.967,46.886) 63.359,46.886 63.752,46.886 64.144,46.886 64.467,47.209 64.79,47.533 65.114,47.856 65.437,48.179 65.76,48.502 66.083,48.826 66.407,49.149 66.73,49.472 67.053,49.795 67.376,50.119 67.521,50.119 v1(67.591,50.189) ; v1(70.208,50.289) 70.519,50.289 70.829,50.289 71.174,50.634 71.519,50.978 71.864,51.323 72.208,51.668 73.15,52.4 79.792,59.042 79.792,59.252 80.137,59.596 80.481,59.941 80.826,60.286 81.171,60.631 81.171,60.997 81.171,61.362 81.171,61.728 81.475,62.032 81.778,62.336 82.082,62.64 82.386,62.943 82.69,63.247 82.69,63.266 v1(82.912,63.488)
VCC_3V3: C_3V3_BULK.1 C_LDO_OUT.1 C_MCU_AVCC.1 C_MCU_DVCC1.1 C_MCU_DVCC2.1 C_TFT_IOVDD.1 C_TFT_VDD.1 J_DEBUG.1 J_DISPLAY.10 J_DISPLAY.11 R_DISPLAY_CS.2 R_DISPLAY_RESET.2 R_MCU_RESET.2 U_LDO.5 U_MAIN.11 U_MAIN.18 U_MAIN.50 | length 129.9
  Top w0.25: 49.775,55.075 49.981,55.108 50.326,55.108 50.671,55.108 U_MAIN.18 50.619,55.15 50.525,55.15 50.432,55.15 50.338,55.15 50.244,55.15 50.15,55.15 50.057,55.15 U_MAIN.18@49.976,55.15 ; U_MAIN.11@49.976,51.65 50.057,51.65 50.15,51.65 50.244,51.65 50.338,51.65 50.432,51.65 50.525,51.65 50.619,51.65 U_MAIN.11 ; U_MAIN.11@50.233,51.65 50.473,51.65 U_MAIN.11 ; U_MAIN.11@51.045,51.65 U_MAIN.11 ; 51.45,51.65 51.369,51.65 51.275,51.65 51.181,51.65 51.088,51.65 50.994,51.65 50.9,51.65 50.806,51.65 U_MAIN.11 ; 63.338,51.612 63.351,51.65 63.432,51.65 63.525,51.65 63.619,51.65 63.713,51.65 63.807,51.65 63.9,51.65 63.994,51.65 U_MAIN.50 64.182,51.65 U_MAIN.50@64.276,51.65
  Top w0.262: 51.686,46.874 51.687,47.214 51.688,47.553 51.689,47.893 51.691,48.232 51.692,48.571 51.693,48.911
  Top w0.275: 51.686,46.874 51.696,46.531 ; 51.693,48.911 51.694,49.25 51.695,49.59
  Top w0.288: 51.695,49.59 51.696,49.929 51.712,50.264 ; 51.696,46.531 51.707,46.188
  Top w0.29: U_MAIN.50@64.276,51.65 64.37,51.608 U_MAIN.50@64.825,51.621
  Top w0.3: 51.712,50.264 51.727,50.599 ; 100.775,52.65 100.837,52.65 100.931,52.65 101.025,52.65 101.119,52.65 101.213,52.65 101.306,52.65 J_DISPLAY.10 101.4,52.8 ; J_DISPLAY.11@101.4,53 J_DISPLAY.11
  Top w0.312: 51.727,50.599 51.743,50.935
  Top w0.35: U_LDO.5 39.1,57.175 39.8,57.35 44,61.9 44.35,62.95 44.175,63.65 43.65,63.825 C_LDO_OUT.1 41.81,62.638 42.045,62.876 42.281,63.114 42.516,63.352 42.751,63.59 43.038,63.617 44,63.825 44.547,63.359 44.782,63.12 45.017,62.88 45.252,62.64 C_3V3_BULK.1 ; v1(45.521,65.251) 45.553,62.465 C_3V3_BULK.1 ; C_MCU_AVCC.1 49.963,51.65 49.975,51.65 ; 49.775,55.075 49.441,54.568 49.441,54.23 49.441,53.892 49.441,53.554 49.441,53.216 49.441,52.878 49.441,52.54 49.441,52.202 49.625,52.018 49.775,51.75 U_MAIN.11@50.233,51.65 ; 49.975,55.15 49.963,55.15 C_MCU_DVCC1.1 48.668,55.392 48.426,55.634 48.433,58.005 48.375,58.4 48.184,58.599 47.939,58.844 47.694,59.089 47.449,59.335 47.204,59.58 46.959,59.825 46.714,60.07 46.1,60.5 45.978,60.805 45.733,61.05 45.488,61.295 45.488,61.572 45.488,61.848 45.488,62.124 C_3V3_BULK.1 ; U_MAIN.11@51.045,51.65 51.613,51.575 51.758,51.27 51.743,50.935 ; 51.45,51.65 51.462,51.645 63.338,51.612 ; 51.707,46.188 51.717,45.845 51.727,45.503 51.738,45.16 51.748,44.817 51.758,44.474 51.989,44.243 52.225,43.875 52.575,43.525 52.68,43.552 52.91,43.322 53.275,43 53.625,42.65 53.601,42.63 53.832,42.4 R_MCU_RESET.2 ; 64.825,51.621 65.62,51.643 C_MCU_DVCC2.1 65.89,51.304 65.89,50.958 65.89,50.612 65.89,50.266 65.89,49.92 65.89,49.575 65.89,49.229 65.89,48.883 65.89,48.537 66.137,48.29 66.383,48.043 66.63,47.796 66.876,47.549 67.123,47.302 67.37,47.054 67.616,46.807 67.863,46.56 68.109,46.313 68.356,46.066 68.602,45.819 68.849,45.572 69.096,45.325 69.342,45.078 69.589,44.831 69.835,44.584 70.082,44.337 70.329,44.09 70.575,43.843 70.822,43.596 71.068,43.349 71.315,43.101 71.561,42.854 71.808,42.607 72.055,42.36 72.301,42.113 72.548,41.866 72.794,41.619 73.041,41.372 73.288,41.125 73.534,40.878 73.781,40.631 74.027,40.384 74.274,40.137 74.521,39.89 74.767,39.643 75.014,39.396 75.358,38.844 75.5,38.8 76.725,38.8 76.91,38.909 76.43,38.92 76.67,39.16 R_DISPLAY_CS.2 77.192,39.4 77.473,39.4 77.755,39.4 78.036,39.4 78.255,39.157 78.3,38.975 78.475,38.8 79.35,38.8 79.593,39.083 79.752,39.242 R_DISPLAY_RESET.2 85.575,39.4 C_TFT_VDD.1 88.687,40.286 90.959,40.272 91.894,41.222 C_TFT_IOVDD.1 93.271,42.781 v1(94.61,42.787) ; v1(95.346,50.965) 95.348,50.967 97.031,52.65 100.65,52.65 100.744,52.65 100.775,52.65 ; 101.4,52.8 101.4,53
  Bottom w0.35: v1(45.521,65.251) 45.576,65.306 48.97,68.7 J_DEBUG.1 ; v1(94.61,42.787) 94.667,42.832 94.667,42.957 95.346,43.636 v1(95.346,50.965)
XT2_IN: U_MAIN.69 Y_XT2.1 | length 6.1
  Top w0.15: U_MAIN.69 v1(58.267,46.111) ; Y_XT2.1 59.4,43.2 59.541,43.341 59.541,43.352 v1(59.671,43.482)
  Bottom w0.15: v1(58.267,46.111) 58.314,46.118 v1(59.671,43.482)
XT2_OUT: U_MAIN.70 Y_XT2.3 | length 3.4
  Top w0.15: Y_XT2.3 56.4,42.847 57.675,44.122 57.675,44.687 U_MAIN.70
pads on no net: J_DISPLAY.1 J_DISPLAY.14 J_DISPLAY.15 J_DISPLAY.16 J_USB.5 J_USB.11 J_USB.NPTH-1 J_USB.NPTH-2 U_LDO.4 U_MAIN.1 U_MAIN.2 U_MAIN.3 U_MAIN.4 U_MAIN.5 U_MAIN.6 U_MAIN.7 U_MAIN.8 U_MAIN.9 U_MAIN.10 U_MAIN.12 U_MAIN.13 U_MAIN.15 U_MAIN.16 U_MAIN.17 U_MAIN.21 U_MAIN.22 U_MAIN.25 U_MAIN.26 U_MAIN.27 U_MAIN.28 U_MAIN.29 U_MAIN.30 U_MAIN.31 U_MAIN.32 U_MAIN.33 U_MAIN.34 U_MAIN.35 U_MAIN.36 U_MAIN.45 U_MAIN.46 U_MAIN.47 U_MAIN.48 U_MAIN.51 U_MAIN.52 U_MAIN.53 U_MAIN.54 U_MAIN.55 U_MAIN.56 U_MAIN.57 U_MAIN.58 U_MAIN.59 U_MAIN.60 U_MAIN.72 U_MAIN.73 U_MAIN.74 U_MAIN.75 U_MAIN.77 U_MAIN.78 U_MAIN.79 U_MAIN.80

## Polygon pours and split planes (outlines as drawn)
GND on Bottom (solid): 107.1,77.1 25.7,77.1 25.7,25.7 107.1,25.7
GND on Bottom (solid): 67.575,70.836 67.457,70.693 67.306,70.569 67.133,70.476 67.01,70.439 67.01,66.071 67.005,66.02 66.99,65.972 66.966,65.927 66.934,65.887 65.609,64.562 65.612,64.533 65.604,64.455 65.582,64.38 65.545,64.311 65.495,64.25 65.434,64.2 65.365,64.163 65.29,64.141 65.212,64.133 65.134,64.141 65.059,64.163 64.99,64.2 64.929,64.25 64.921,64.26 64.921,61.958 64.969,61.984 65.044,62.006 65.122,62.014 65.157,62.011 68.018,64.872 68.018,69.495 67.995,69.514 67.945,69.575 67.908,69.644 67.886,69.719 67.878,69.797 67.886,69.875 67.908,69.95 67.945,70.019 67.995,70.08 68.056,70.13 68.125,70.167 68.2,70.189 68.22,70.191
GND on Bottom (solid): 59.6,48.517 59.592,48.517 59.068,47.993 59.082,47.997 59.16,48.005 59.238,47.997 59.313,47.975 59.382,47.938 59.443,47.888 59.493,47.827 59.53,47.758 59.534,47.743 59.534,48.285 59.543,48.373 59.568,48.457
GND on Bottom (solid): 58.279,47.204 57.906,46.831 57.906,46.279 57.935,46.333 57.985,46.394 58.045,46.444 58.114,46.481 58.189,46.504 58.267,46.511 58.346,46.504 58.421,46.481 58.49,46.444 58.55,46.394 58.6,46.333 58.637,46.264 58.66,46.189 58.667,46.111 58.661,46.046 58.832,45.714 58.85,45.774 58.88,45.831 58.886,45.839 58.886,45.859 58.886,46.096 58.886,46.333 58.886,46.57 58.886,46.672 58.838,46.72 58.694,46.864 58.568,46.991 58.556,46.992 58.481,47.014 58.412,47.051 58.351,47.101 58.301,47.162

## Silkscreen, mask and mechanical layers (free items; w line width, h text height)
Top Overlay:
  text "2L • BOTTOM GND POUR" at 48.4,75.4 h0.48
  text "ER-CON14HB-1 • 4-WIRE SPI" at 84.4,75.4 h0.55
  text "ER-TFT020-3" at 81.4,28.9 h0.58
  text "QUICK CONFIGURE • SCREEN" at 66.4,27.4 h0.72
